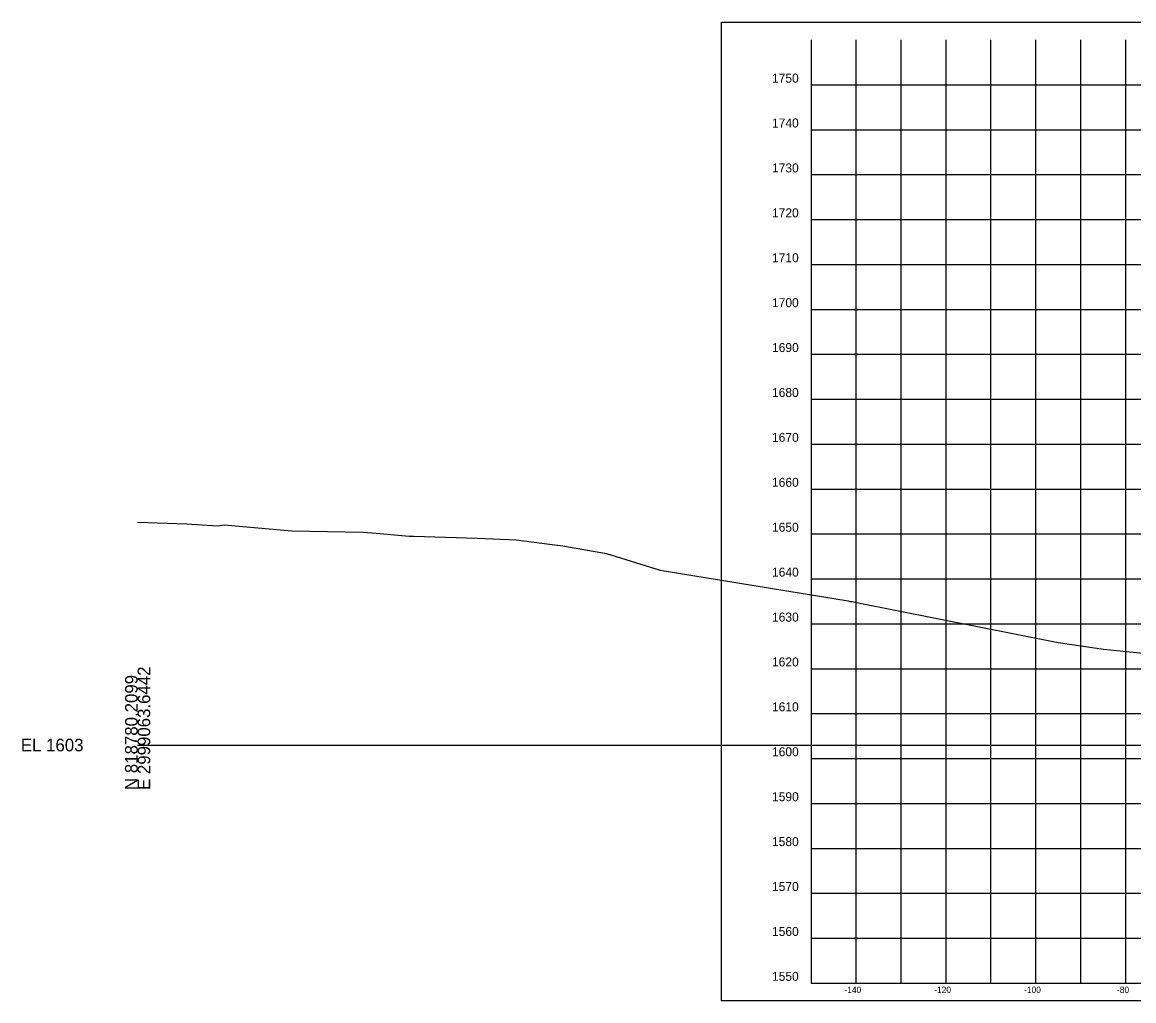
# Model space of a CAD drawing. Extents: x -26 to 1067, y -71 to 1837.
# Drawn here: x -25.7 to 221.8, y -56.9 to 160.9 of the extents above; entities that cross this region are included whole.
import ezdxf

# ---------------------------------------------------------------- set-up
doc = ezdxf.new("R2010")
doc.units = 0
for name, color, linetype in [('DESIGN - SHEET - Corner Text', 7, 'Continuous'), ('DESIGN - SHEET - Light Grid', 7, 'Continuous'), ('DESIGN - SHEET - Linework', 7, 'Continuous'), ('DESIGN - SHEET - Plot Shape', 7, 'Continuous'), ('SURVEY - GROUND - Top of Ground', 7, 'Continuous')]:
    doc.layers.add(name, color=color, linetype=linetype)

msp = doc.modelspace()

# ---------------------------------------------------------------- linework, layer by layer
at = {"layer": 'DESIGN - SHEET - Light Grid'}
msp.add_line((0, 0), (300, 0), dxfattribs=at)
at = {"layer": 'DESIGN - SHEET - Linework'}
for p, q in [((160, -53), (160, 157)), ((170, -53), (170, 157)), ((180, -53), (180, 157)), ((190, -53), (190, 157)), ((200, -53), (200, 157)), ((210, -53), (210, 157)), ((220, -53), (220, 157)), ((150, 147), (450, 147)), ((150, 137), (450, 137)), ((150, 127), (450, 127)), ((150, 117), (450, 117)), ((150, 107), (450, 107)), ((150, 97), (450, 97)), ((150, 87), (450, 87)), ((150, 77), (450, 77)), ((150, 67), (450, 67)), ((150, 57), (450, 57)), ((150, 47), (450, 47)), ((150, 37), (450, 37)), ((150, 27), (450, 27)), ((150, 17), (450, 17)), ((150, 7), (450, 7)), ((150, -3), (450, -3)), ((150, -13), (450, -13)), ((150, -23), (450, -23)), ((150, -33), (450, -33)), ((150, -43), (450, -43))]:
    msp.add_line(p, q, dxfattribs=at)
msp.add_lwpolyline([(150, 157), (150, -53), (450, -53), (450, 157)], dxfattribs=at)
at = {"layer": 'DESIGN - SHEET - Plot Shape'}
msp.add_lwpolyline([(130, 160.94), (470, 160.94), (470, -56.94), (130, -56.94)], close=True, dxfattribs=at)
at = {"layer": 'SURVEY - GROUND - Top of Ground'}
msp.add_lwpolyline([(0, 49.65), (10.98, 49.27), (17.76, 48.8), (19.3, 49.06), (34.31, 47.7), (50.24, 47.43), (53.12, 47.16), (60.44, 46.51), (61.47, 46.54), (75.63, 46.04), (84.31, 45.71), (91.73, 44.69), (94.67, 44.37), (104.39, 42.67), (116.31, 38.95), (158.22, 32.08), (158.67, 31.99), (159.07, 31.94), (160.09, 31.75), (204.97, 22.82), (215.09, 21.34), (223.88, 20.45)], dxfattribs=at)

# ---------------------------------------------------------------- texts
at = {"layer": 'DESIGN - SHEET - Corner Text'}
for s, height, p in [('1750', 2, (141.25, 147.5)), ('1740', 2, (141.25, 137.5)), ('1730', 2, (141.25, 127.5)), ('1720', 2, (141.25, 117.5)), ('1710', 2, (141.25, 107.5)), ('1700', 2, (141.25, 97.5)), ('1690', 2, (141.25, 87.5)), ('1680', 2, (141.25, 77.5)), ('1670', 2, (141.25, 67.5)), ('1660', 2, (141.25, 57.5)), ('1650', 2, (141.25, 47.5)), ('1640', 2, (141.25, 37.5)), ('1630', 2, (141.25, 27.5)), ('1620', 2, (141.25, 17.5)), ('1610', 2, (141.25, 7.5)), ('1600', 2, (141.25, -2.5)), ('1590', 2, (141.25, -12.5)), ('1580', 2, (141.25, -22.5)), ('1570', 2, (141.25, -32.5)), ('1560', 2, (141.25, -42.5)), ('1550', 2, (141.25, -52.5)), ('-140', 1.4, (157.37, -55.2)), ('-120', 1.4, (177.37, -55.2)), ('-100', 1.4, (197.37, -55.2)), ('-80', 1.4, (218.06, -55.2))]:
    msp.add_text(s, height=height, dxfattribs=at).set_placement(p)
at = {"layer": 'DESIGN - SHEET - Light Grid'}
for s, p in [('N 818780.2099', (0, -10)), ('E 2999063.6442', (2.8, -10))]:
    msp.add_text(s, height=2.8, rotation=90, dxfattribs=at).set_placement(p)
msp.add_text('EL 1603', height=2.8, dxfattribs=at).set_placement((-26, -1.4))

doc.saveas('drawing.dxf')
